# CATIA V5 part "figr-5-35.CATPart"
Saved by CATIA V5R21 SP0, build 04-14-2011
Part number: Part1
Bounding box of the stored display mesh (mm): x -39.481 to 85.69, y 0 to 131.399, z 0 to 44
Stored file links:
  D:\CATIA V5R21 E-RESOURCES\CATIA-V5R21\catia-v5r21-prt\c05-catia-v5r20-prt\catia-v5r21-figr-5-35.CATPart
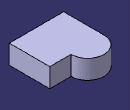
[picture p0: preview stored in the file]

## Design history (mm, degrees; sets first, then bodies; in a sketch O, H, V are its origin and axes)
Body1 (main body)
  Sketch1 on xy-plane, origin (0, 0, 0), H (1, 0, 0), V (0, 1, 0)
    point P1 (-39.4814, 0)
    line L1 (-39.4814, 0) -> (36.6898, 0)
    line L2 (36.6898, 0) -> (36.6898, 93.3015)
    arc A1 centre (-1.4186, 93.3015) radius 38.1084 from (36.6898, 93.3015) to (-39.4814, 95.1659) ccw
    line L3 (-39.4814, 95.1659) -> (-39.4814, 0)
    coincidence: P1 H
    horizontal: L1 H
    vertical: L2 V, L3 V
    tangency: A1 L2
  Pad1: profile Sketch1, direction (0, 0, 1), length 44
  Pad2: profile face of Pad1, direction along edge [face of Pad1 | face of Pad1] reversed, length -49, opposite side length -19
